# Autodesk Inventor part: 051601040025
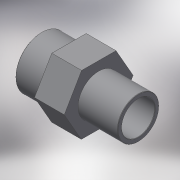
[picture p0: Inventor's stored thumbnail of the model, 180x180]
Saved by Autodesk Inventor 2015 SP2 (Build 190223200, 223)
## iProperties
Created: 2017-10
Part Number: 051601040025
Material: Generic
Description: PLASSON THR. REDUCING NIPPLE 4"-2.1/2" PVC
Document SubType Name: Modeling
Designer: KIM
Density: 1 g/cm^3
Appearance: Default
Author: KIM
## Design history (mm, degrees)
derived "051601.ipt"
feature "Solid1::051601.ipt"
tag "TaggingFeature1"
body "Solid1"
other parameters: "d0" = 94, "d13" = 0, "d14" = 0.75184, "d17" = 33, "d18" = 49.2, "d19" = 113.03, "d21" = 75.184, "d23" = 90.424, "d24" = 60.1472, "d25" = 41, "d26" = -33, "R_1" = 75.184, "lt_1" = 33, "lt_" = 41, "H_" = 94, "R_" = 113.03
